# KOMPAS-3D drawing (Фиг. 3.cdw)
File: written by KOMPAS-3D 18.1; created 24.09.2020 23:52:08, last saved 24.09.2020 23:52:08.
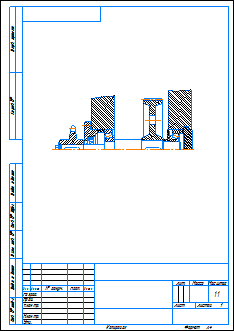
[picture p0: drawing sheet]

Sheet 1: A4, portrait

Document properties: Автор: user; Полное имя файла: C:\Users\user\Desktop\Задания\Фиг. 3.cdw

Title block, sheet 1: scale: 1:1; Количество листов документа: 1; Форматы листов документа: A4

Dimensions and other numbers on the sheet: 1:1; 1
